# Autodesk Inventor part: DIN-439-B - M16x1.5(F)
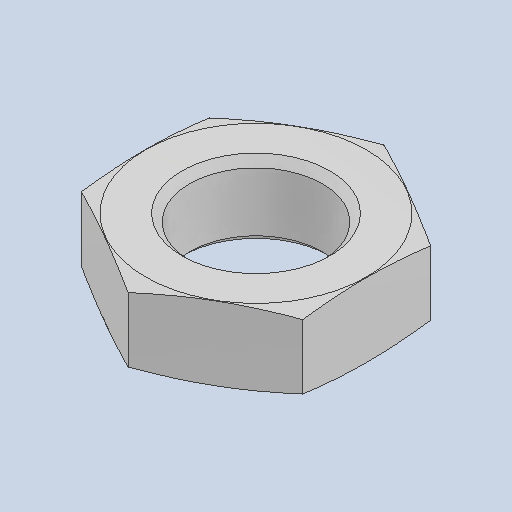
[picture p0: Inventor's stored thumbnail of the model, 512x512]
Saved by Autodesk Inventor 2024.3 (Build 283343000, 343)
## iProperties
Created: 2024-12
Part Number: DIN-439-B - M16x1.5(F)
Material: Generic
Description: DIN-439-B - M16x1.5(F)
Document SubType Name: Modeling
Designer: ruhr
Density: 1 g/cm^3
Appearance: Default
Author: ruhr
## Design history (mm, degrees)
feature "DIN-439-B - M16x1.5(F)"
body "Solid1"
